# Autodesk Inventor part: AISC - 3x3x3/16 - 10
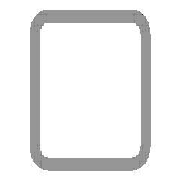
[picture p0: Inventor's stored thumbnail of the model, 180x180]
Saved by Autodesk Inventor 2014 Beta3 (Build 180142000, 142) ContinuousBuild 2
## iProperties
Created: 2011-01
Part Number: AISC - 3x3x3/16 - 10
Material: Steel, Mild
Description: Tube
Document SubType Name: Modeling
Standard: ANSI
Designer: Beta-8540w
Standards Organization: ANSI
Language: en-US
Size Designation: 3x3x3/16
Categories: <MemberInstance><Categories><Category DisplayName="Structural Shapes" InternalName="089c4875-fa83-4c05-b084-43b9cc11f5ed" Mnemonic="GRDR"><CategoryParameter Dis
Stock Number: 3x3x3/16
Density: 7.86 g/cm^3
Appearance: Steel
IsCustomPart: 1
_CCFamilyMember: 9
_CCFamilyDisplayName: ANSI AISC (Square) - Tube
_FrameMemberDoc: Frame Member File
_Version: 15.0.0
_GetPNFromCC: 1
G_L: 10.000 in
G_W: 3.000 in
G_H: 3.000 in
Author: Beta-8540w
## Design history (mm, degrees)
node "Start plane"
node "End plane"
sketch "Sketch"
  geometry: L1 (-38.1, -28.575)-(-38.1, 28.575); L2 (-28.575, 38.1)-(28.575, 38.1); L3 (38.1, 28.575)-(38.1, -28.575); L4 (28.575, -38.1)-(-28.575, -38.1); L5 (-28.575, 33.337)-(28.575, 33.338); L6 (33.338, 28.575)-(33.338, -28.575); L7 (28.575, -33.337)-(-28.575, -33.338); L8 (-33.338, -28.575)-(-33.338, 28.575); L9 (0, 56.102)-(0, -56.102) reference; L10 (-56.102, 0)-(56.102, 0) reference; A1 r 9.525 centre (-28.575, -28.575) between (-38.1, -28.575) and (-28.575, -38.1); A2 r 9.525 centre (-28.575, 28.575) between (-28.575, 38.1) and (-38.1, 28.575); A3 r 9.525 centre (28.575, 28.575) between (38.1, 28.575) and (28.575, 38.1); A4 r 9.525 centre (28.575, -28.575) between (28.575, -38.1) and (38.1, -28.575); A5 r 4.763 centre (-28.575, 28.575) between (-28.575, 33.337) and (-33.338, 28.575); A6 r 4.763 centre (28.575, 28.575) between (33.338, 28.575) and (28.575, 33.338); A7 r 4.763 centre (28.575, -28.575) between (28.575, -33.337) and (33.338, -28.575); A8 r 4.763 centre (-28.575, -28.575) between (-33.338, -28.575) and (-28.575, -33.338)
  constraints: 16 end point, 16 point on circle, 8 centre point, 8 tangent, 4 parallel, 3 equal radius, 2 perpendicular, 7 other
  dimensions: "d10" = 76.2 distance between parallel lines of L2 L4 (= G_H); "d11" = 76.2 distance between parallel lines of L1 L3 (= G_W); "d12" = 4.7625 distance between parallel lines of L3 L6 (= G_T); "d15" = 38.1 distance between parallel lines of L2 L10 (= 0.5 x d10); "d16" = 38.1 distance between parallel lines of L9 L3 (= 0.5 x d11); "d17" = 9.525 radius of A1 (= G_IR)
extrude "Body" new body sketch "Sketch" stored distance "d3" = 254 (= G_L); taper "d4" = 0 deg
node "Driven Length"
  sketch "Sketch3"
    geometry: L1 (0, 0)-(10, 0) reference
    constraints: 2 end point, 1 horizontal
  workplane "Work Plane3"
  sketch "Sketch4"
    geometry: L1 (-2, 0)-(12, 0) reference; L2 (-2, 254)-(12, 254) reference
    dimensions: "d19" = 254 distance between parallel lines of L1 L2 (derived)
body "Solid1"
other parameters: "G_W" = 76.2 [user parameter; used in 1 equation term], "G_H" = 76.2 [user parameter; used in 1 equation term], "G_T" = 4.7625 [user parameter; used in 1 equation term], "G_IR" = 9.525 [user parameter; used in 1 equation term], "G_L" = 254 (= d19) [user parameter; used in 1 equation term], "G_OFFSET_START" = 0 [user parameter; used in 1 equation term], "G_OFFSET_END" = 0 [user parameter; used in 1 equation term], "d13" = 0 (computed from G_OFFSET_START), "d14" = 254 (= G_OFFSET_END + B_L), "B_L" = 254 [user parameter; used in 1 equation term], "d18" = 90 deg
